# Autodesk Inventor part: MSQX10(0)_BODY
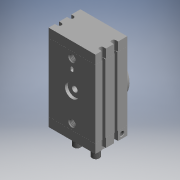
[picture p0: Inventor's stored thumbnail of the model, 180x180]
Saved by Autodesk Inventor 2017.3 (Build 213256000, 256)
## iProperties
Part Number: MSQX10(0)_BODY
Material: Generic
Catalog Web Link: www.cadenas.de
Description: MSQ BODY-Low-Speed Rotary Table Rack & Pinion Style
Vendor: SMC
Document SubType Name: Modeling
Designer: partserver
Manufacturer: SMC
Mass: 155.652 g
Surface Area: 269.512 cm^2
Volume: 155.652 cm^3
Density: 1 g/cm^3
Appearance: PSOLRGB-192-192-192
Category: PARTsolutions
Company: SMC
Title: MSQX10_BODY
Author: Cadenas PARTsolutions
Comments: Low-Speed Rotary Table Rack & Pinion Style
PSOL_IDENT_0: {$CADENAS_DATA\23d-libs\smc_jp\actuator\rotary_actuator\msqx\parts\msqx_body.prj},179 {VTYP=3D},{NB=
PSOL_IDENT_1: MSQX10(0)_BODY},{LINA=MSQX10_BODY},{NN=MSQ BODY},{DATE=09.12.2020 02:49:36},{GEOMDATE=04.12.2019 00:
PSOL_IDENT_2: 28:12},{VERSION=},{LINEID=160},{WBVAR=OMSC,THREAD},{WBNUMERIC=}  {NB=MSQX10(0)_BODY},{LINA=MSQX10_BO
PSOL_IDENT_3: DY},{KT=DUMMY},{ORDER=MSQX10},{SIZE=10},{OMSC=},{THREAD=0},{AA=55.4},{A=50},{AU=8.6},{AV=20.0},{AW=1
PSOL_IDENT_4: 5.5},{AX=12},{AY=4},{BA=9.5},{BB=34.5},{BC=27.8},{BD=60},{BE=27},{CA=4.5},{CB=28.5},{D=45h9},{D1=45}
PSOL_IDENT_5: ,{DD=46h9},{DD1=46},{DE=20H9},{DE1=20},{DF=6},{DG=15H9},{DG1=15},{FA=8.0},{FB=4.0},{FC=3.0},{FD=4.5}
PSOL_IDENT_6: ,{H=13},{J=6.8},{JA=11.0},{JB=6.5},{JC=M8x1.25},{JC1=8},{JCP=1.25},{JD=12},{JJ=M5x0.8},{JJ1=5},{JJP=
PSOL_IDENT_7: 0.800},{JU=M8x1},{JU1=8},{JUP=1.0},{P=M5x0.8},{P1=5.000},{Q=34},{S=92},{SD=9.0},{SE=13},{SF=45},{SU=
PSOL_IDENT_8: 17.7},{UU=47},{WA=15.0},{WB=3H9},{WB1=3},{WC=3.5},{WD=M5x0.8},{WD1=5},{WDP=0.80},{WE=8.0},{WF=32},{X
PSOL_IDENT_9: A=27},{XB=3H9},{XB1=3},{XC=3.5},{YA=19},{YB=3H9},{YB1=3},{YC=3.5},{FU=31.5},{DA=46h9},{DA1=46},{DB=4
PSOL_IDENT_10: 5h9},{DB1=45},{DC=20H9},{DC1=20},{DDD=35h9},{DDD1=35},{HHA=11.5},{HB=20},{HC=5},{HD=59},{HE=5.5},{F1=
PSOL_IDENT_11: 6.917},{F2=5},{Y1=8},{Y2=12},{H1=5.000},{H2=5.000},{PD=0.3},{S1=15.5},{S2=1.6},{S3=2.0}
NB: MSQX10(0)_BODY
NN: MSQ BODY
NT: Low-Speed Rotary Table Rack & Pinion Style
NBSYN: $ORDER.($THREAD.)_BODY
LINA: MSQX10_BODY
CATALOG: SMC (JP
SIZE: 10
OMSC: (-) Without order
THREAD: on
AA: 55.4
A: 50
AU: 8.6
AV: 20
AW: 15.5
AX: 12
AY: 4
BA: 9.5
BB: 34.5
BC: 27.8
BD: 60
BE: 27
CA: 4.5
CB: 28.5
D: 45h9
D1: 45
DD: 46h9
DD1: 46
DE: 20H9
DE1: 20
DF: 6
DG: 15H9
DG1: 15
FA: 8
FB: 4
FC: 3
FD: 4.5
H: 13
J: 6.8
JA: 11
JB: 6.5
JC: M8x1.25
JC1: 8
JCP: 1.25
JD: 12
JJ: M5x0.8
JJ1: 5
JJP: 0.8
JU: M8x1
JU1: 8
JUP: 1
P: M5x0.8
P1: 5
Q: 34
S: 92
SD: 9
SE: 13
SF: 45
SU: 17.7
UU: 47
WA: 15
WB: 3H9
WB1: 3
WC: 3.5
WD: M5x0.8
WD1: 5
WDP: 0.8
WE: 8
WF: 32
XA: 27
XB: 3H9
XB1: 3
XC: 3.5
YA: 19
YB: 3H9
YB1: 3
YC: 3.5
FU: 31.5
DA: 46h9
DA1: 46
DB: 45h9
DB1: 45
DC: 20H9
DC1: 20
DDD: 35h9
DDD1: 35
HHA: 11.5
HB: 20
HC: 5
HD: 59
HE: 5.5
F1: 6.917
F2: 5
Y1: 8
Y2: 12
H1: 5
H2: 5
S1: 15.5
S2: 1.6
S3: 2
SUPPLIER: SMC
ARTICLENO: MSQX10(0)_BODY
BOMINFO: MSQX10_BODY
CREATOR: CADENAS GmbH
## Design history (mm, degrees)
sketch "Sketch_1"
  geometry: L1 (-25, 20.5)-(-25, 10.5); L2 (-25, 10.5)-(-23.97, 10.5); L3 (-23.97, 7.5)-(-25, 7.5); L4 (-25, 7.5)-(-25, 0); L5 (-25, 0)-(25, 0); L6 (25, 0)-(25, 7.5); L7 (25, 7.5)-(23.97, 7.5); L8 (23.97, 10.5)-(25, 10.5); L9 (25, 10.5)-(25, 20.5); L10 (25, 20.5)-(23.97, 20.5); L11 (23.97, 23.5)-(25, 23.5); L12 (25, 23.5)-(25, 34); L13 (25, 34)-(-25, 34); L14 (-25, 34)-(-25, 23.5); L15 (-25, 23.5)-(-23.97, 23.5); L16 (-23.97, 20.5)-(-25, 20.5); A1 r 2.1 centre (-22.5, 9) between (-23.97, 7.5) and (-23.97, 10.5); A2 r 2.1 centre (22.5, 9) between (23.97, 10.5) and (23.97, 7.5); A3 r 2.1 centre (22.5, 22) between (23.97, 23.5) and (23.97, 20.5); A4 r 2.1 centre (-22.5, 22) between (-23.97, 20.5) and (-23.97, 23.5)
  constraints: 32 end point, 8 point on circle, 4 centre point
extrude "Extrusion1" join sketch "Sketch_1" distance "d0" = 92; taper "d1" = 0 deg
sketch "Sketch_41"
  geometry: L1 (34, 0)-(38.5, 0); L2 (38.5, 0)-(38.5, -23); L3 (38.5, -23)-(34, -23); L4 (34, -23)-(34, 0); L5 (34, 0)-(38.5, 0)
  constraints: 10 end point
revolve "Revolution1" sketch "Sketch_41" stored, may be unused: angle "d2" = 360 deg
sketch "Sketch_26"
  geometry: L1 (-26, 35)-(-26, -1); L2 (-26, -1)-(26, -1); L3 (26, -1)-(26, 35); L4 (26, 35)-(-26, 35); L5 (-25, 19.75)-(-25, 11.25); L6 (-25, 11.25)-(-22.5, 11.25); L7 (-22.5, 6.75)-(-25, 6.75); L8 (-25, 6.75)-(-25, 0); L9 (-25, 0)-(25, 0); L10 (25, 0)-(25, 6.75); L11 (25, 6.75)-(22.5, 6.75); L12 (22.5, 11.25)-(25, 11.25); L13 (25, 11.25)-(25, 19.75); L14 (25, 19.75)-(22.5, 19.75); L15 (22.5, 24.25)-(25, 24.25); L16 (25, 24.25)-(25, 34); L17 (25, 34)-(-25, 34); L18 (-25, 34)-(-25, 24.25); L19 (-25, 24.25)-(-22.5, 24.25); L20 (-22.5, 19.75)-(-25, 19.75); A1 r 2.25 centre (-22.5, 9) between (-22.5, 6.75) and (-22.5, 11.25); A2 r 2.25 centre (22.5, 9) between (22.5, 11.25) and (22.5, 6.75); A3 r 2.25 centre (22.5, 22) between (22.5, 24.25) and (22.5, 19.75); A4 r 2.25 centre (-22.5, 22) between (-22.5, 19.75) and (-22.5, 24.25)
  constraints: 40 end point, 8 point on circle, 4 centre point
extrude "Extrusion2" cut sketch "Sketch_26" distance "d3" = 9.5; taper "d4" = 0 deg
sketch "Sketch_27"
  geometry: L1 (-26, 35)-(-26, -1); L2 (-26, -1)-(26, -1); L3 (26, -1)-(26, 35); L4 (26, 35)-(-26, 35); L5 (-25, 19.75)-(-25, 11.25); L6 (-25, 11.25)-(-22.5, 11.25); L7 (-22.5, 6.75)-(-25, 6.75); L8 (-25, 6.75)-(-25, 0); L9 (-25, 0)-(25, 0); L10 (25, 0)-(25, 6.75); L11 (25, 6.75)-(22.5, 6.75); L12 (22.5, 11.25)-(25, 11.25); L13 (25, 11.25)-(25, 19.75); L14 (25, 19.75)-(22.5, 19.75); L15 (22.5, 24.25)-(25, 24.25); L16 (25, 24.25)-(25, 34); L17 (25, 34)-(-25, 34); L18 (-25, 34)-(-25, 24.25); L19 (-25, 24.25)-(-22.5, 24.25); L20 (-22.5, 19.75)-(-25, 19.75); A1 r 2.25 centre (-22.5, 9) between (-22.5, 6.75) and (-22.5, 11.25); A2 r 2.25 centre (22.5, 9) between (22.5, 11.25) and (22.5, 6.75); A3 r 2.25 centre (22.5, 22) between (22.5, 24.25) and (22.5, 19.75); A4 r 2.25 centre (-22.5, 22) between (-22.5, 19.75) and (-22.5, 24.25)
  constraints: 40 end point, 8 point on circle, 4 centre point
extrude "Extrusion3" cut sketch "Sketch_27" distance "d5" = 9.5; taper "d6" = 0 deg
sketch "Sketch_28"
  geometry: L1 (-25, 7.5)-(-25, 0); L2 (-25, 0)-(25, 0); L3 (25, 0)-(25, 7.5); L4 (25, 7.5)-(23.97, 7.5); L5 (23.97, 10.5)-(25, 10.5); L6 (25, 10.5)-(25, 20.5); L7 (25, 20.5)-(23.97, 20.5); L8 (23.97, 23.5)-(25, 23.5); L9 (25, 23.5)-(25, 34); L10 (25, 34)-(-25, 34); L11 (-25, 34)-(-25, 23.5); L12 (-25, 23.5)-(-23.97, 23.5); L13 (-23.97, 20.5)-(-25, 20.5); L14 (-25, 20.5)-(-25, 10.5); L15 (-25, 10.5)-(-23.97, 10.5); L16 (-23.97, 7.5)-(-25, 7.5); L17 (-24.9, 0.1)-(24.9, 0.1); L18 (24.9, 0.1)-(24.9, 7.4); L19 (24.9, 7.4)-(24.01, 7.4); L20 (24.01, 10.6)-(24.9, 10.6); L21 (24.9, 10.6)-(24.9, 20.4); L22 (24.9, 20.4)-(24.01, 20.4); L23 (24.01, 23.6)-(24.9, 23.6); L24 (24.9, 23.6)-(24.9, 33.9); L25 (24.9, 33.9)-(-24.9, 33.9); L26 (-24.9, 33.9)-(-24.9, 23.6); L27 (-24.9, 23.6)-(-24.01, 23.6); L28 (-24.01, 20.4)-(-24.9, 20.4); L29 (-24.9, 20.4)-(-24.9, 10.6); L30 (-24.9, 10.6)-(-24.01, 10.6); L31 (-24.01, 7.4)-(-24.9, 7.4); L32 (-24.9, 7.4)-(-24.9, 0.1); A1 r 2.1 centre (22.5, 9) between (23.97, 10.5) and (23.97, 7.5); A2 r 2.1 centre (22.5, 22) between (23.97, 23.5) and (23.97, 20.5); A3 r 2.1 centre (-22.5, 22) between (-23.97, 20.5) and (-23.97, 23.5); A4 r 2.1 centre (-22.5, 9) between (-23.97, 7.5) and (-23.97, 10.5); A5 r 2.2 centre (22.5, 9) between (24.01, 10.6) and (24.01, 7.4); A6 r 2.2 centre (22.5, 22) between (24.01, 23.6) and (24.01, 20.4); A7 r 2.2 centre (-22.5, 22) between (-24.01, 20.4) and (-24.01, 23.6); A8 r 2.2 centre (-22.5, 9) between (-24.01, 7.4) and (-24.01, 10.6)
  constraints: 64 end point, 16 point on circle, 8 centre point
extrude "Extrusion4" cut sketch "Sketch_28" distance "d7" = 0.05; taper "d8" = 0 deg
sketch "Sketch_29"
  geometry: L1 (-25, 7.5)-(-25, 0); L2 (-25, 0)-(25, 0); L3 (25, 0)-(25, 7.5); L4 (25, 7.5)-(23.97, 7.5); L5 (23.97, 10.5)-(25, 10.5); L6 (25, 10.5)-(25, 20.5); L7 (25, 20.5)-(23.97, 20.5); L8 (23.97, 23.5)-(25, 23.5); L9 (25, 23.5)-(25, 34); L10 (25, 34)-(-25, 34); L11 (-25, 34)-(-25, 23.5); L12 (-25, 23.5)-(-23.97, 23.5); L13 (-23.97, 20.5)-(-25, 20.5); L14 (-25, 20.5)-(-25, 10.5); L15 (-25, 10.5)-(-23.97, 10.5); L16 (-23.97, 7.5)-(-25, 7.5); L17 (-24.9, 0.1)-(24.9, 0.1); L18 (24.9, 0.1)-(24.9, 7.4); L19 (24.9, 7.4)-(24.01, 7.4); L20 (24.01, 10.6)-(24.9, 10.6); L21 (24.9, 10.6)-(24.9, 20.4); L22 (24.9, 20.4)-(24.01, 20.4); L23 (24.01, 23.6)-(24.9, 23.6); L24 (24.9, 23.6)-(24.9, 33.9); L25 (24.9, 33.9)-(-24.9, 33.9); L26 (-24.9, 33.9)-(-24.9, 23.6); L27 (-24.9, 23.6)-(-24.01, 23.6); L28 (-24.01, 20.4)-(-24.9, 20.4); L29 (-24.9, 20.4)-(-24.9, 10.6); L30 (-24.9, 10.6)-(-24.01, 10.6); L31 (-24.01, 7.4)-(-24.9, 7.4); L32 (-24.9, 7.4)-(-24.9, 0.1); A1 r 2.1 centre (22.5, 9) between (23.97, 10.5) and (23.97, 7.5); A2 r 2.1 centre (22.5, 22) between (23.97, 23.5) and (23.97, 20.5); A3 r 2.1 centre (-22.5, 22) between (-23.97, 20.5) and (-23.97, 23.5); A4 r 2.1 centre (-22.5, 9) between (-23.97, 7.5) and (-23.97, 10.5); A5 r 2.2 centre (22.5, 9) between (24.01, 10.6) and (24.01, 7.4); A6 r 2.2 centre (22.5, 22) between (24.01, 23.6) and (24.01, 20.4); A7 r 2.2 centre (-22.5, 22) between (-24.01, 20.4) and (-24.01, 23.6); A8 r 2.2 centre (-22.5, 9) between (-24.01, 7.4) and (-24.01, 10.6)
  constraints: 64 end point, 16 point on circle, 8 centre point
extrude "Extrusion5" cut sketch "Sketch_29" distance "d9" = 0.05; taper "d10" = 0 deg
sketch "Sketch_32"
  geometry: C1 r 7.75 at (10, 15.5); 1 further point
  constraints: 1 centre point
extrude "Extrusion6" join sketch "Sketch_32" distance "d11" = 1.6; taper "d12" = 0 deg
pattern_linear "Rectangular Pattern1" dims "d15" = 20, "d18" = 0
sketch "Sketch_36"
  geometry: C1 r 8.75 at (10, 15.5); C2 r 7.65 at (10, 15.5); 2 further points
  constraints: 2 centre point
extrude "Extrusion7" cut sketch "Sketch_36" distance "d19" = 0.1; taper "d20" = 0 deg
pattern_linear "Rectangular Pattern2" dims "d23" = 20, "d26" = 0
sketch "Sketch_51"
  geometry: C1 r 7.75 at (10, 15.5); 1 further point
  constraints: 1 centre point
extrude "Extrusion8" join sketch "Sketch_51" distance "d27" = 2; taper "d28" = 0 deg
pattern_linear "Rectangular Pattern3" dims "d31" = 20, "d34" = 0
sketch "Sketch_3"
  geometry: L1 (4, 12.036)-(10, 8.572); L2 (10, 8.572)-(16, 12.036); L3 (16, 12.036)-(16, 18.964); L4 (16, 18.964)-(10, 22.428); L5 (10, 22.428)-(4, 18.964); L6 (4, 18.964)-(4, 12.036)
  constraints: 12 end point
extrude "Extrusion9" join sketch "Sketch_3" distance "d35" = 8.6; taper "d36" = 0 deg
sketch "Sketch_4"
  geometry: L1 (-16, 12.036)-(-10, 8.572); L2 (-10, 8.572)-(-4, 12.036); L3 (-4, 12.036)-(-4, 18.964); L4 (-4, 18.964)-(-10, 22.428); L5 (-10, 22.428)-(-16, 18.964); L6 (-16, 18.964)-(-16, 12.036)
  constraints: 12 end point
extrude "Extrusion10" join sketch "Sketch_4" distance "d37" = 8.6; taper "d38" = 0 deg
sketch "Sketch_5"
  geometry: L1 (-63.7, 15.5)-(-46, 15.5); L2 (-46, 15.5)-(-46, 11.5); L3 (-46, 11.5)-(-63.087, 11.5); L4 (-63.087, 11.5)-(-63.7, 12.114); L5 (-63.7, 12.114)-(-63.7, 15.5); L6 (-63.7, 15.5)-(-46, 15.5)
  constraints: 12 end point
revolve "Revolution2" sketch "Sketch_5" stored, may be unused: angle "d39" = 360 deg
thread "Thread1" dims "d40" = 17.0865, "d41" = 0
sketch "Sketch_6"
  geometry: L1 (-63.7, 15.5)-(-46, 15.5); L2 (-46, 15.5)-(-46, 11.5); L3 (-46, 11.5)-(-63.087, 11.5); L4 (-63.087, 11.5)-(-63.7, 12.114); L5 (-63.7, 12.114)-(-63.7, 15.5); L6 (-63.7, 15.5)-(-46, 15.5)
  constraints: 12 end point
revolve "Revolution3" sketch "Sketch_6" stored, may be unused: angle "d42" = 360 deg
thread "Thread2" dims "d43" = 17.0865, "d44" = 0
sketch "Sketch_43"
  geometry: L1 (8, 14.345)-(10, 13.191); L2 (10, 13.191)-(12, 14.345); L3 (12, 14.345)-(12, 16.655); L4 (12, 16.655)-(10, 17.809); L5 (10, 17.809)-(8, 16.655); L6 (8, 16.655)-(8, 14.345)
  constraints: 12 end point
extrude "Extrusion11" cut sketch "Sketch_43" distance "d45" = 5; taper "d46" = 0 deg
sketch "Sketch_44"
  geometry: L1 (-12, 14.345)-(-10, 13.191); L2 (-10, 13.191)-(-8, 14.345); L3 (-8, 14.345)-(-8, 16.655); L4 (-8, 16.655)-(-10, 17.809); L5 (-10, 17.809)-(-12, 16.655); L6 (-12, 16.655)-(-12, 14.345)
  constraints: 12 end point
extrude "Extrusion12" cut sketch "Sketch_44" distance "d47" = 5; taper "d48" = 0 deg
sketch "Sketch_7"
  geometry: L1 (-46, 27.8)-(-39.807, 27.8); L2 (-39.807, 27.8)-(-41, 25.733); L3 (-41, 25.733)-(-45.567, 25.733); L4 (-45.567, 25.733)-(-46, 25.3); L5 (-46, 25.3)-(-46, 27.8); L6 (-46, 27.8)-(-39.807, 27.8)
  constraints: 12 end point
revolve "Revolution4" sketch "Sketch_7" stored, may be unused: angle "d49" = 360 deg
thread "Thread3" dims "d50" = 4.567, "d51" = 0
sketch "Sketch_8"
  geometry: L1 (-46, 27.8)-(-39.807, 27.8); L2 (-39.807, 27.8)-(-41, 25.733); L3 (-41, 25.733)-(-45.567, 25.733); L4 (-45.567, 25.733)-(-46, 25.3); L5 (-46, 25.3)-(-46, 27.8); L6 (-46, 27.8)-(-39.807, 27.8)
  constraints: 12 end point
revolve "Revolution5" sketch "Sketch_8" stored, may be unused: angle "d52" = 360 deg
thread "Thread4" dims "d53" = 4.567, "d54" = 0
sketch "Sketch_15"
  geometry: L1 (13.5, 34)-(13.5, 24.807); L2 (13.5, 24.807)-(11.433, 26); L3 (11.433, 26)-(11.433, 33.567); L4 (11.433, 33.567)-(11, 34); L5 (11, 34)-(13.5, 34); L6 (13.5, 34)-(13.5, 24.807)
  constraints: 12 end point
revolve "Revolution6" sketch "Sketch_15" stored, may be unused: angle "d55" = 360 deg
thread "Thread5" dims "d56" = 7.567, "d57" = 0
pattern_linear "Rectangular Pattern4" dims "d60" = 60, "d63" = 27
sketch "Sketch22"
  geometry: 1 further point
hole "Hole1" sketch "Sketch22" at (25, 6.5) diameter "d64" = 6.8; stored, may be unused: countersink angle "d68" = 90 deg, drill point angle "d70" = 0 deg; dims "d65" = 6, "d66" = 11, "d67" = 6.5, "d69" = 22
sketch "Sketch_20"
  geometry: L1 (0, 0)-(0, 12); L2 (0, 12)-(3.324, 12); L3 (3.324, 12)-(3.324, 0.676); L4 (3.324, 0.676)-(4, 0); L5 (4, 0)-(0, 0); L6 (0, 0)-(0, 12)
  constraints: 12 end point
revolve "Revolution7" sketch "Sketch_20" stored, may be unused: angle "d71" = 360 deg
thread "Thread6" dims "d72" = 11.3235, "d73" = 0
sketch "Sketch25"
  geometry: 1 further point
hole "Hole2" sketch "Sketch25" at (25, 66.5) diameter "d74" = 6.8; stored, may be unused: countersink angle "d78" = 90 deg, drill point angle "d80" = 0 deg; dims "d75" = 6, "d76" = 11, "d77" = 6.5, "d79" = 22
sketch "Sketch_22"
  geometry: L1 (0, 0)-(0, 12); L2 (0, 12)-(3.324, 12); L3 (3.324, 12)-(3.324, 0.676); L4 (3.324, 0.676)-(4, 0); L5 (4, 0)-(0, 0); L6 (0, 0)-(0, 12)
  constraints: 12 end point
revolve "Revolution8" sketch "Sketch_22" stored, may be unused: angle "d81" = 360 deg
thread "Thread7" dims "d82" = 11.3235, "d83" = 0
sketch "Sketch28"
  geometry: 1 further point
hole "Hole3" sketch "Sketch28" at (25, -36.5) diameter "d84" = 6; stored, may be unused: countersink angle "d88" = 90 deg, drill point angle "d90" = 0 deg; dims "d85" = 6, "d86" = 15, "d87" = 3, "d89" = 47
sketch "Sketch_24"
  geometry: L1 (-1.5, -19)-(-1.5, -21); L2 (1.5, -21)-(1.5, -19); A1 r 1.5 centre (0, -19) between (1.5, -19) and (-1.5, -19); A2 r 1.5 centre (0, -21) between (-1.5, -21) and (1.5, -21)
  constraints: 4 end point, 4 point on circle, 2 centre point
extrude "Extrusion13" cut sketch "Sketch_24" distance "d91" = 3.5; taper "d92" = 0 deg
sketch "Sketch_25"
  geometry: L1 (-21.567, 19.445)-(-20.153, 18.031); L2 (-18.031, 20.153)-(-19.445, 21.567); A1 r 1.5 centre (-20.506, 20.506) between (-19.445, 21.567) and (-21.567, 19.445); A2 r 1.5 centre (-19.092, 19.092) between (-20.153, 18.031) and (-18.031, 20.153)
  constraints: 4 end point, 4 point on circle, 2 centre point
extrude "Extrusion14" cut sketch "Sketch_25" distance "d93" = 3.5; taper "d94" = 0 deg
sketch "Sketch_35"
  geometry: L1 (25, -41.5)-(20, -41.5); L2 (20, -41.5)-(20, -39.433); L3 (20, -39.433)-(24.567, -39.433); L4 (24.567, -39.433)-(25, -39); L5 (25, -39)-(25, -41.5); L6 (25, -41.5)-(20, -41.5)
  constraints: 12 end point
revolve "Revolution9" sketch "Sketch_35" stored, may be unused: angle "d95" = 360 deg
thread "Thread8" dims "d96" = 4.567, "d97" = 0
sketch "Sketch_54"
  geometry: L1 (-20, -41.5)-(-25, -41.5); L2 (-25, -41.5)-(-25, -39); L3 (-25, -39)-(-24.567, -39.433); L4 (-24.567, -39.433)-(-20, -39.433); L5 (-20, -39.433)-(-20, -41.5); L6 (-20, -41.5)-(-25, -41.5)
  constraints: 12 end point
revolve "Revolution10" sketch "Sketch_54" stored, may be unused: angle "d98" = 360 deg
thread "Thread9" dims "d99" = 4.567, "d100" = 0
node "BODY_HOLDER_XY"
node "BODY_HOLDER_YZ"
node "BODY_HOLDER_ZX"
node "BODY_HOLDER_X"
node "BODY_HOLDER_Y"
node "BODY_HOLDER_Z"
node "BODY_HOLDER_Center"
node "BODY_TABLE_XY"
node "BODY_TABLE_YZ"
node "BODY_TABLE_ZX"
node "BODY_TABLE_X"
node "BODY_TABLE_Y"
node "BODY_TABLE_Z"
node "BODY_TABLE_Center"
node "body_sw1_XY"
node "body_sw1_YZ"
node "body_sw1_ZX"
node "body_sw1_X"
node "body_sw1_Y"
node "body_sw1_Z"
node "body_sw1_Center"
node "body_sw2_XY"
node "body_sw2_YZ"
node "body_sw2_ZX"
node "body_sw2_X"
node "body_sw2_Y"
node "body_sw2_Z"
node "body_sw2_Center"
node "body_dummy_XY"
node "body_dummy_YZ"
node "body_dummy_ZX"
node "body_dummy_X"
node "body_dummy_Y"
node "body_dummy_Z"
node "body_dummy_Center"
node "plug1_XY"
node "plug1_YZ"
node "plug1_ZX"
node "plug1_X"
node "plug1_Y"
node "plug1_Z"
node "plug1_Center"
node "plug2_XY"
node "plug2_YZ"
node "plug2_ZX"
node "plug2_X"
node "plug2_Y"
node "plug2_Z"
node "plug2_Center"
node "plug3_XY"
node "plug3_YZ"
node "plug3_ZX"
node "plug3_X"
node "plug3_Y"
node "plug3_Z"
node "plug3_Center"
node "plug4_XY"
node "plug4_YZ"
node "plug4_ZX"
node "plug4_X"
node "plug4_Y"
node "plug4_Z"
node "plug4_Center"
body "Solid1"
other parameters: "d101" = 0, "d102" = 0, "d103" = 0, "d104" = 0, "d105" = 0, "d106" = 0, "d107" = 0
